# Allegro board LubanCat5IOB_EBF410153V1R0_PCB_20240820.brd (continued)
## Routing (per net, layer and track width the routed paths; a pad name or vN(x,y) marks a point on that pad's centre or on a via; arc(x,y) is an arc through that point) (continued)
MIPI_DPHY0_RX_CLKP: length 147.9
  TOP w0.114: J3.13 44.87,64.5 44.95,64.42 44.95,63.83 v2(44.68,63.56) ; v1(158.6,77.76) 158.79,77.57 159.36,77.57 159.74,77.19 159.74,76.18 159.87,76.05 160.06,76.05 160.2,76.18 160.2,77.19 160.47,77.47 162.17,77.47 162.42,77.22 164.93,77.22 arc(165,77.23) 165.07,77.28 165.08,77.29 arc(165.15,77.33) 165.22,77.35 J32.9
  ART03 w0.102: v2(44.68,63.56) 44.93,63.31 44.93,61.21 45.38,60.77 51.83,60.77 55.87,64.81 65.28,64.81 68.91,61.18 75,61.18 78.04,60.65 81.08,61.18 81.91,61.18 84.66,60.7 87.42,61.18 88.27,61.18 92.28,61.88 96.3,61.18 100.33,61.18 103.7,61.76 107.07,61.18 114.21,61.18 114.58,61.55 114.58,62.89 114.6,63.12 114.96,65.22 114.6,67.33 114.58,67.55 114.58,70.07 117.96,73.45 123.46,73.45 123.92,73.9 140.37,73.9 140.74,74.27 140.74,76.27 140.94,76.47 148.3,76.47 148.93,75.83 159.35,75.83 159.72,76.2 159.72,77.12 159.27,77.56 158.79,77.56 v1(158.6,77.76)
MIPI_DPHY0_RX_D0N: length 147.8
  TOP w0.114: J32.12 165.22,75.85 arc(165.15,75.86) 165.08,75.9 165.07,75.92 arc(165,75.96) 164.93,75.98 163.29,75.98 arc(163.12,75.94) 162.97,75.84 v1(162.81,75.69) ; J3.25 47.27,64.5 47.19,64.42 47.19,63.83 v2(47.46,63.56)
  ART03 w0.102: v1(162.81,75.69) 162.96,75.83 164.25,75.83 164.69,76.27 164.69,78.92 163.97,79.64 156.5,79.64 156.13,79.28 156.13,78.2 155.93,77.99 153.03,77.99 152.91,78.11 152.91,78.83 152.63,79.11 152.23,79.11 151.95,78.83 151.95,78.11 151.83,77.99 151.66,77.99 151.54,78.11 151.54,78.47 151.26,78.75 150.86,78.75 150.58,78.47 150.58,78.11 150.46,77.99 149.92,77.99 149.09,78.83 136.38,78.83 136.04,78.49 136.04,76.8 135.84,76.6 118.01,76.6 112.12,70.7 112.12,67.19 arc(112.11,67.17) 112.11,67.16 111.86,65.69 arc(111.85,65.61) 111.86,65.53 112.11,64.06 arc(112.11,64.05) 112.12,64.03 112.12,63.43 111.82,63.13 107.25,63.13 arc(107.24,63.13) 107.22,63.14 103.78,63.73 arc(103.7,63.74) 103.62,63.73 100.18,63.14 arc(100.16,63.13) 100.14,63.13 96.49,63.13 arc(96.47,63.13) 96.45,63.14 92.37,63.85 arc(92.28,63.85) 92.2,63.85 88.12,63.14 arc(88.1,63.13) 88.08,63.13 87.25,63.13 84.66,62.69 82.08,63.13 80.91,63.13 78.04,62.64 75.17,63.13 70.3,63.13 66.87,66.56 54,66.56 50.26,62.82 47.42,62.82 47.29,62.95 47.29,63.39 v2(47.46,63.56)
MIPI_DPHY0_RX_D0P: length 147.8
  TOP w0.114: J32.11 165.22,76.35 arc(165.15,76.33) 165.08,76.29 165.07,76.28 arc(165,76.23) 164.93,76.22 163.29,76.22 arc(163.12,76.25) 162.97,76.35 v1(162.81,76.51) ; v2(46.68,63.56) 46.95,63.83 46.95,64.42 46.87,64.5 J3.23
  ART03 w0.102: v2(46.68,63.56) 46.89,63.56 47.01,63.45 47.01,62.83 47.3,62.54 50.38,62.54 54.12,66.28 66.75,66.28 70.18,62.85 75.14,62.85 78.04,62.35 80.93,62.85 82.05,62.85 84.66,62.4 87.27,62.85 88.08,62.85 arc(88.13,62.86) 88.17,62.86 92.25,63.57 arc(92.28,63.57) 92.32,63.57 96.4,62.86 arc(96.44,62.86) 96.49,62.85 100.14,62.85 arc(100.18,62.86) 100.22,62.86 103.66,63.46 arc(103.7,63.46) 103.73,63.46 107.17,62.86 arc(107.21,62.86) 107.25,62.85 111.94,62.85 112.39,63.31 112.39,64.03 arc(112.39,64.07) 112.39,64.11 112.13,65.57 arc(112.13,65.61) 112.13,65.64 112.39,67.11 arc(112.39,67.15) 112.39,67.19 112.39,70.59 118.12,76.32 135.95,76.32 136.32,76.68 136.32,78.37 136.5,78.55 148.97,78.55 149.81,77.71 150.57,77.71 150.86,78 150.86,78.36 150.98,78.48 151.14,78.48 151.26,78.36 151.26,78 151.55,77.71 151.95,77.71 152.23,78 152.23,78.71 152.35,78.83 152.52,78.83 152.63,78.71 152.63,78 152.92,77.71 156.05,77.71 156.41,78.08 156.41,79.16 156.62,79.36 163.86,79.36 164.41,78.81 164.41,76.39 164.13,76.11 162.92,76.11 162.81,76.22 v1(162.81,76.51)
MIPI_DPHY0_RX_D1N: length 147.7
  TOP w0.114: J32.8 165.22,77.85 arc(165.15,77.86) 165.08,77.9 165.07,77.92 arc(165,77.96) 164.93,77.98 164.55,77.98 arc(164.47,77.94) 164.43,77.86 arc(164.4,77.77) 164.32,77.74 164.1,77.74 arc(164.01,77.77) 163.98,77.86 arc(163.94,77.94) 163.86,77.98 163.29,77.98 arc(163.12,77.94) 162.97,77.84 v1(162.81,77.69) ; v2(46.57,62.54) 46.28,62.84 46.28,63.97 46.39,64.09 46.39,64.42 46.47,64.5 J3.21
  ART03 w0.102: v2(46.57,62.54) 46.32,62.29 46.32,62.01 46.53,61.8 46.81,61.8 arc(46.89,61.84) 46.93,61.92 arc(46.96,62.01) 47.05,62.04 47.22,62.04 arc(47.3,62.01) 47.33,61.92 arc(47.37,61.84) 47.45,61.8 47.62,61.8 arc(47.71,61.84) 47.74,61.92 arc(47.78,62.01) 47.86,62.04 48.03,62.04 arc(48.11,62.01) 48.15,61.92 arc(48.18,61.84) 48.27,61.8 48.44,61.8 arc(48.52,61.84) 48.55,61.92 arc(48.59,62.01) 48.67,62.04 48.84,62.04 arc(48.93,62.01) 48.96,61.92 arc(49,61.84) 49.08,61.8 49.25,61.8 arc(49.33,61.84) 49.37,61.92 arc(49.4,62.01) 49.49,62.04 49.65,62.04 arc(49.74,62.01) 49.77,61.92 arc(49.81,61.84) 49.89,61.8 51.23,61.8 55.26,65.83 65.88,65.83 69.41,62.3 75.09,62.3 78.04,61.78 80.98,62.3 82,62.3 84.66,61.83 87.32,62.3 88.17,62.3 92.28,63.01 96.4,62.3 100.23,62.3 103.7,62.9 107.17,62.3 113.08,62.3 113.28,62.5 113.28,64.24 arc(113.28,64.26) 113.28,64.27 113.04,65.64 arc(113.04,65.73) 113.04,65.81 113.28,67.18 arc(113.28,67.2) 113.28,67.22 113.28,70.53 117.83,75.07 123.18,75.07 123.73,75.63 136.74,75.63 137.01,75.9 137.01,77.38 137.31,77.69 137.9,77.69 138.18,77.41 138.18,76.05 138.3,75.94 138.76,75.94 138.96,76.14 138.96,77.16 139.33,77.53 148.98,77.53 149.38,77.13 156.95,77.13 157.15,77.33 157.15,78.3 157.58,78.73 161.7,78.73 162.1,78.32 162.1,77.48 162.36,77.23 163.47,77.23 163.68,77.43 163.68,77.76 163.47,77.96 163.08,77.96 v1(162.81,77.69)
MIPI_DPHY0_RX_D1P: length 147.7
  TOP w0.114: v2(45.79,62.54) 46.04,62.79 46.04,64.07 46.15,64.19 46.15,64.42 46.07,64.5 J3.19 ; J32.7 165.22,78.35 arc(165.15,78.33) 165.08,78.29 165.07,78.28 arc(165,78.23) 164.93,78.22 163.29,78.22 arc(163.12,78.25) 162.97,78.35 v1(162.81,78.51)
  ART03 w0.102: v1(162.81,78.51) 163.08,78.24 163.59,78.24 163.96,77.87 163.96,77.32 163.59,76.95 162.24,76.95 161.82,77.37 161.82,78.21 161.58,78.45 157.7,78.45 157.43,78.18 157.43,77.22 157.06,76.85 149.26,76.85 148.87,77.25 139.45,77.25 139.24,77.04 139.24,76.02 138.88,75.66 138.19,75.66 137.9,75.94 137.9,77.29 137.79,77.41 137.43,77.41 137.29,77.27 137.29,75.78 136.86,75.35 123.85,75.35 123.29,74.79 117.95,74.79 113.56,70.41 113.56,67.22 arc(113.56,67.17) 113.56,67.13 113.32,65.76 arc(113.32,65.73) 113.32,65.69 113.56,64.32 arc(113.56,64.28) 113.56,64.24 113.56,62.38 113.2,62.02 107.14,62.02 103.7,62.61 100.25,62.02 96.37,62.02 92.28,62.73 88.2,62.02 87.34,62.02 84.66,61.55 81.98,62.02 81,62.02 78.04,61.5 75.07,62.02 69.29,62.02 65.76,65.55 55.37,65.55 51.35,61.52 46.41,61.52 46.04,61.89 46.04,62.29 v2(45.79,62.54)
MIPI_DPHY0_RX_D2N: length 147.9
  TOP w0.114: v2(44.26,62.55) 43.99,62.82 43.99,64.42 44.07,64.5 J3.9 ; J32.17 165.22,73.35 arc(165.15,73.36) 165.08,73.4 165.07,73.42 arc(165,73.46) 164.93,73.48 163.29,73.48 arc(163.12,73.44) 162.97,73.34 v1(162.81,73.19)
  ART03 w0.102: v2(44.26,62.55) 44.14,62.67 44.14,63.25 43.75,63.64 43.06,63.64 42.7,63.28 42.7,60.33 43.17,59.86 52.37,59.86 56.24,63.72 65.14,63.72 68.54,60.31 74.92,60.31 78.04,59.77 81.15,60.31 81.83,60.31 84.66,59.82 87.49,60.31 88.34,60.31 92.28,61 96.22,60.31 100.4,60.31 103.7,60.89 106.99,60.31 114.42,60.31 115.32,61.21 115.32,62.86 115.33,63.02 115.71,65.22 115.33,67.42 115.32,67.59 115.32,69.19 118.61,72.48 141.34,72.48 141.71,72.85 141.71,73.98 141.91,74.18 143.15,74.18 143.93,74.95 159.77,74.95 160.07,74.65 160.07,73.67 160.44,73.31 162.7,73.31 v1(162.81,73.19)
MIPI_DPHY0_RX_D2P: length 147.8
  TOP w0.114: J3.7 43.67,64.5 43.75,64.42 43.75,62.82 v2(43.48,62.55) ; J32.16 165.22,73.85 arc(165.15,73.83) 165.08,73.79 165.07,73.78 arc(165,73.73) 164.93,73.72 163.29,73.72 arc(163.12,73.75) 162.97,73.85 v1(162.81,74.01)
  ART03 w0.102: v1(162.81,74.01) 162.81,73.69 162.71,73.59 162.22,73.59 arc(162.15,73.61) 162.12,73.68 arc(162.09,73.75) 162.03,73.78 161.81,73.78 arc(161.74,73.75) 161.71,73.68 arc(161.69,73.61) 161.62,73.59 160.55,73.59 160.35,73.79 160.35,74.77 159.88,75.23 143.81,75.23 143.04,74.46 141.79,74.46 141.43,74.1 141.43,72.96 141.22,72.76 118.49,72.76 115.04,69.31 115.04,67.57 115.05,67.39 115.43,65.22 115.05,63.06 115.04,62.87 115.04,61.33 114.3,60.59 107.02,60.59 103.7,61.17 100.38,60.59 96.25,60.59 92.28,61.28 88.32,60.59 87.47,60.59 84.66,60.11 81.86,60.59 81.13,60.59 78.04,60.06 74.95,60.59 68.66,60.59 65.25,64 56.12,64 52.26,60.14 43.28,60.14 42.98,60.44 42.98,60.67 arc(43.01,60.75) 43.09,60.78 arc(43.17,60.82) 43.21,60.9 43.21,61.08 arc(43.17,61.16) 43.09,61.19 arc(43.01,61.22) 42.98,61.31 42.98,61.48 arc(43.01,61.56) 43.09,61.6 arc(43.17,61.63) 43.21,61.71 43.21,61.89 arc(43.17,61.97) 43.09,62 arc(43.01,62.04) 42.98,62.12 42.98,63.16 43.18,63.36 43.63,63.36 43.86,63.13 43.86,62.65 43.76,62.55 v2(43.48,62.55)
MIPI_DPHY0_RX_D3N: length 147.8
  TOP w0.114: J32.20 165.22,71.85 arc(165.15,71.86) 165.08,71.9 165.07,71.92 arc(165,71.96) 164.93,71.98 162.02,71.98 arc(161.85,71.94) 161.7,71.84 v1(161.54,71.69) ; J3.5 43.27,64.5 43.19,64.42 43.19,64 42.82,63.63 41.49,63.63 v2(41.22,63.36)
  ART03 w0.102: v2(41.22,63.36) 41.47,63.61 41.76,63.61 42.04,63.33 42.04,59.84 42.86,59.02 52.98,59.02 56.95,62.98 64.47,62.98 67.94,59.5 74.84,59.5 arc(74.85,59.5) 74.87,59.5 77.96,58.96 arc(78.04,58.96) 78.12,58.96 81.2,59.5 arc(81.22,59.5) 81.24,59.5 81.75,59.5 arc(81.76,59.5) 81.78,59.5 84.58,59.01 arc(84.66,59.01) 84.74,59.01 87.54,59.5 arc(87.56,59.5) 87.58,59.5 88.41,59.5 92.28,60.17 96.15,59.5 100.47,59.5 103.7,60.06 106.92,59.5 114.78,59.5 116.05,60.77 116.05,62.86 arc(116.05,62.88) 116.06,62.9 116.45,65.14 arc(116.45,65.22) 116.45,65.31 116.06,67.55 arc(116.05,67.57) 116.05,67.59 116.05,68.38 119.42,71.74 142.95,71.74 143.89,72.68 143.89,73.64 144.24,73.99 157.93,73.99 159.97,71.96 161.28,71.96 v1(161.54,71.69)
MIPI_DPHY0_RX_D3P: length 147.8
  TOP w0.114: v2(41.22,64.14) 41.49,63.87 42.72,63.87 42.95,64.1 42.95,64.42 42.87,64.5 J3.3 ; J32.19 165.22,72.35 arc(165.15,72.33) 165.08,72.29 165.07,72.28 arc(165,72.23) 164.93,72.22 162.02,72.22 arc(161.85,72.25) 161.7,72.35 v1(161.54,72.51)
  ART03 w0.102: v2(41.22,64.14) 41.47,63.89 41.87,63.89 42.32,63.45 42.32,59.96 42.98,59.3 43.33,59.3 arc(43.39,59.32) 43.42,59.39 arc(43.44,59.45) 43.5,59.48 43.73,59.48 arc(43.8,59.45) 43.82,59.39 arc(43.85,59.32) 43.91,59.3 44.14,59.3 arc(44.2,59.32) 44.23,59.39 arc(44.25,59.45) 44.32,59.48 44.55,59.48 arc(44.61,59.45) 44.63,59.39 arc(44.66,59.32) 44.72,59.3 52.87,59.3 56.83,63.26 64.58,63.26 68.06,59.78 74.84,59.78 arc(74.88,59.78) 74.92,59.77 78,59.24 arc(78.04,59.24) 78.07,59.24 81.16,59.77 arc(81.2,59.78) 81.24,59.78 81.75,59.78 arc(81.79,59.78) 81.83,59.77 84.63,59.29 arc(84.66,59.29) 84.7,59.29 87.5,59.77 arc(87.54,59.78) 87.58,59.78 88.39,59.78 92.28,60.46 96.18,59.78 100.45,59.78 103.7,60.35 106.95,59.78 114.67,59.78 115.77,60.89 115.77,62.86 arc(115.77,62.9) 115.78,62.95 116.17,65.19 arc(116.17,65.22) 116.17,65.26 115.78,67.5 arc(115.77,67.54) 115.77,67.59 115.77,68.49 119.3,72.02 142.84,72.02 143.61,72.8 143.61,73.75 144.13,74.27 158.05,74.27 160.08,72.24 161.28,72.24 v1(161.54,72.51)
MIPI_DPHY0_TX_CLKN: length 66.4
  TOP w0.114: v1(8.99,71.42) 8.7,71.7 7.94,71.7 7.81,71.57 J14.24 ; J3.41 50.47,64.5 50.39,64.42 50.39,60.53 49.2,59.34 37.14,59.34 36.86,59.61 36.86,60.14 36.73,60.28 36.54,60.28 36.41,60.14 36.41,59.61 36.13,59.34 35.7,59.34 v1(35.43,59.07)
  ART03 w0.102: v1(35.43,59.07) 35.16,59.34 33.7,59.34 33.44,59.6 21.89,59.6 21.56,59.93 21.56,62.38 21.37,62.58 15.54,62.58 15.14,62.98 15.14,67.48 14.94,67.68 11.72,67.68 11.35,68.05 11.35,68.55 11.64,68.83 12.68,68.83 12.8,68.95 12.8,69.12 12.68,69.24 11.64,69.24 11.35,69.52 11.35,69.92 11.64,70.2 12.68,70.2 12.8,70.32 12.8,70.49 12.68,70.61 11.64,70.61 11.35,70.89 11.35,71.47 11.15,71.67 9.24,71.67 v1(8.99,71.42)
MIPI_DPHY0_TX_CLKP: length 66.4
  TOP w0.114: v1(35.43,59.89) 35.75,59.58 36.03,59.58 36.17,59.71 36.17,60.24 36.44,60.52 36.83,60.52 37.11,60.24 37.11,59.71 37.24,59.58 49.1,59.58 50.15,60.63 50.15,63.32 arc(50.11,63.43) 49.99,63.48 arc(49.88,63.52) 49.83,63.63 49.83,63.77 arc(49.88,63.89) 49.99,63.93 arc(50.11,63.98) 50.15,64.09 50.15,64.42 50.07,64.5 J3.39 ; v1(8.99,72.23) 8.7,71.94 7.94,71.94 7.81,72.07 J14.23
  ART03 w0.102: v1(8.99,72.23) 9.27,71.95 11.27,71.95 11.63,71.58 11.63,71.01 11.75,70.89 12.8,70.89 13.08,70.61 13.08,70.21 12.8,69.93 11.75,69.93 11.63,69.81 11.63,69.64 11.75,69.52 12.8,69.52 13.08,69.24 13.08,68.84 12.8,68.55 11.75,68.55 11.63,68.43 11.63,68.16 11.84,67.96 15.05,67.96 15.42,67.59 15.42,63.1 15.66,62.85 21.49,62.85 21.84,62.5 21.84,60.05 22.01,59.88 33.55,59.88 33.81,59.62 35.16,59.62 v1(35.43,59.89)
MIPI_DPHY0_TX_D0N: length 66.4
  TOP w0.114: J14.27 7.81,70.07 7.94,70.2 9.26,70.2 v1(9.58,69.89) ; J3.51 52.47,64.5 52.39,64.42 52.39,59.7 49.75,57.05 44,57.05 43.87,56.92 43.87,56.58 43.59,56.3 43.2,56.3 42.93,56.58 42.93,56.92 42.79,57.05 42.55,57.05 42.42,56.92 42.42,56.45 42.14,56.17 41.75,56.17 41.48,56.45 41.48,56.92 41.34,57.05 39.91,57.05 v1(39.62,56.76)
  ART03 w0.102: v1(39.62,56.76) 39.27,57.11 33.97,57.11 33.63,57.46 33.63,58.32 33.44,58.51 20.89,58.51 20.56,58.85 20.56,61.39 20.23,61.71 14.78,61.71 14.4,62.09 14.4,66.55 14.11,66.84 10.73,66.84 10.36,67.21 10.36,69.98 10.16,70.18 9.87,70.18 v1(9.58,69.89)
MIPI_DPHY0_TX_D0P: length 66.5
  TOP w0.114: J3.49 52.07,64.5 52.15,64.42 52.15,59.8 49.65,57.29 43.9,57.29 43.63,57.02 43.63,56.68 43.49,56.54 43.3,56.54 43.17,56.68 43.17,57.02 42.89,57.29 42.45,57.29 42.18,57.02 42.18,56.55 42.04,56.42 41.85,56.42 41.72,56.55 41.72,57.02 41.44,57.29 39.91,57.29 v1(39.62,57.58) ; J14.26 7.81,70.57 7.94,70.44 9.31,70.44 v1(9.58,70.71)
  ART03 w0.102: v1(9.58,70.71) 9.82,70.46 10.28,70.46 10.64,70.1 10.64,67.32 10.85,67.12 14.22,67.12 14.68,66.66 14.68,62.21 14.9,61.99 20.35,61.99 20.83,61.5 20.83,58.96 21.01,58.79 33.55,58.79 33.91,58.43 33.91,57.57 34.09,57.39 34.4,57.39 arc(34.49,57.43) 34.53,57.52 arc(34.56,57.61) 34.65,57.65 34.81,57.65 arc(34.9,57.61) 34.93,57.52 arc(34.97,57.43) 35.06,57.39 35.21,57.39 arc(35.3,57.43) 35.34,57.52 arc(35.38,57.61) 35.47,57.65 35.62,57.65 arc(35.71,57.61) 35.75,57.52 arc(35.78,57.43) 35.87,57.39 39.44,57.39 v1(39.62,57.58)
MIPI_DPHY0_TX_D1N: length 66.4
  TOP w0.114: v1(37.72,57.91) 38.01,58.19 49.47,58.19 51.59,60.32 51.59,64.42 51.67,64.5 J3.47 ; v1(9.75,72.92) 9.46,73.2 7.94,73.2 7.81,73.07 J14.21
  ART03 w0.102: v1(37.72,57.91) 37.45,58.17 36.31,58.17 35.94,58.54 35.94,60.43 35.5,60.87 22.85,60.87 22.53,61.19 22.53,63.63 22.34,63.82 16.54,63.82 16.17,64.19 16.17,68.11 15.79,68.49 13.91,68.49 13.54,68.86 13.54,71.54 13.42,71.66 12.53,71.66 12.24,71.94 12.24,72.34 12.53,72.63 13.42,72.63 13.54,72.75 13.54,72.98 13.33,73.18 10.02,73.18 v1(9.75,72.92)
MIPI_DPHY0_TX_D1P: length 66.4
  TOP w0.114: J3.45 51.27,64.5 51.35,64.42 51.35,60.42 49.37,58.43 38.01,58.43 v1(37.72,58.72) ; v1(9.75,73.73) 9.46,73.44 7.94,73.44 7.81,73.57 J14.20
  ART03 w0.102: v1(9.75,73.73) 10.02,73.46 11.66,73.46 arc(11.73,73.49) 11.75,73.56 arc(11.78,73.62) 11.85,73.65 12.07,73.65 arc(12.13,73.62) 12.16,73.56 arc(12.19,73.49) 12.25,73.46 12.47,73.46 arc(12.54,73.49) 12.57,73.56 arc(12.59,73.62) 12.66,73.65 12.88,73.65 arc(12.95,73.62) 12.97,73.56 arc(13,73.49) 13.07,73.46 13.45,73.46 13.82,73.09 13.82,72.63 13.53,72.35 12.64,72.35 12.52,72.23 12.52,72.06 12.64,71.94 13.53,71.94 13.82,71.66 13.82,68.98 14.02,68.77 15.9,68.77 16.45,68.23 16.45,64.3 16.65,64.1 22.46,64.1 22.81,63.74 22.81,61.31 22.96,61.15 35.61,61.15 36.22,60.54 36.22,58.66 36.42,58.45 37.45,58.45 v1(37.72,58.72)
MIPI_DPHY0_TX_D2N: length 66.4
  TOP w0.114: v1(8.9,74.42) 8.61,74.7 7.94,74.7 7.81,74.57 J14.18 ; v1(37.72,60.18) 38.02,60.48 47.82,60.48 49.19,61.86 49.19,64.42 49.27,64.5 J3.35
  ART03 w0.102: v1(8.9,74.42) 9.17,74.68 9.84,74.68 10.29,74.23 14.12,74.23 14.33,74.03 14.33,69.65 14.69,69.28 16.8,69.28 17.17,68.91 17.17,65.19 17.55,64.81 23.1,64.81 23.39,64.52 23.39,62.12 23.8,61.71 24.52,61.71 24.8,61.99 24.8,62.61 24.92,62.73 25.09,62.73 25.21,62.61 25.21,61.98 25.48,61.71 25.96,61.71 26.25,61.99 26.25,62.61 26.37,62.73 26.54,62.73 26.65,62.61 26.65,61.99 26.94,61.71 27.34,61.71 27.62,61.99 27.62,62.63 27.72,62.73 27.92,62.73 28.03,62.63 28.03,61.99 28.31,61.71 30.05,61.71 30.33,61.99 30.33,62.58 30.45,62.7 30.62,62.7 30.74,62.58 30.74,61.99 31.02,61.71 31.53,61.71 31.81,61.99 31.81,62.61 31.93,62.73 32.1,62.73 32.22,62.61 32.22,61.99 32.5,61.71 35.7,61.71 36.96,60.45 37.45,60.45 v1(37.72,60.18)
MIPI_DPHY0_TX_D2P: length 66.4
  TOP w0.114: v1(37.72,61) 37.99,60.72 47.72,60.72 48.95,61.96 48.95,64.42 48.87,64.5 J3.33 ; v1(8.9,75.23) 8.61,74.94 7.94,74.94 7.81,75.07 J14.17
  ART03 w0.102: v1(8.9,75.23) 9.17,74.96 9.95,74.96 10.4,74.51 10.63,74.51 arc(10.7,74.54) 10.73,74.62 arc(10.76,74.69) 10.83,74.72 11.04,74.72 arc(11.11,74.69) 11.14,74.62 arc(11.17,74.54) 11.24,74.51 11.44,74.51 arc(11.51,74.54) 11.54,74.62 arc(11.57,74.69) 11.65,74.72 11.85,74.72 arc(11.92,74.69) 11.95,74.62 arc(11.98,74.54) 12.05,74.51 14.24,74.51 14.61,74.15 14.61,69.76 14.81,69.56 16.92,69.56 17.45,69.03 17.45,65.31 17.67,65.09 23.22,65.09 23.67,64.63 23.67,62.23 23.92,61.99 24.4,61.99 24.52,62.11 24.52,62.72 24.8,63.01 25.2,63.01 25.49,62.72 25.49,62.1 25.59,61.99 25.85,61.99 25.97,62.11 25.97,62.72 26.25,63.01 26.65,63.01 26.93,62.72 26.93,62.11 27.05,61.99 27.22,61.99 27.34,62.11 27.34,62.74 27.61,63.01 28.04,63.01 28.31,62.74 28.31,62.11 28.42,61.99 29.93,61.99 30.05,62.11 30.05,62.7 30.33,62.98 30.73,62.98 31.02,62.7 31.02,62.11 31.13,61.99 31.42,61.99 31.54,62.11 31.54,62.72 31.82,63.01 32.22,63.01 32.5,62.72 32.5,62.11 32.62,61.99 35.81,61.99 37.08,60.73 37.45,60.73 v1(37.72,61)
MIPI_DPHY0_TX_D3N: length 66.4
  TOP w0.114: v1(8.58,68.36) 8.29,68.65 7.89,68.65 7.81,68.57 J14.30 ; J3.31 48.47,64.5 48.39,64.42 48.39,62.66 47.36,61.62 39.96,61.62 v1(39.67,61.33)
  ART03 w0.102: v1(8.58,68.36) 8.31,68.63 7.85,68.63 7.62,68.4 7.62,68.18 arc(7.65,68.1) 7.73,68.06 arc(7.82,68.03) 7.85,67.95 7.85,67.77 arc(7.82,67.69) 7.73,67.66 arc(7.65,67.62) 7.62,67.54 7.62,67.36 arc(7.65,67.28) 7.73,67.25 arc(7.82,67.22) 7.85,67.13 7.85,66.96 arc(7.82,66.88) 7.73,66.84 arc(7.65,66.81) 7.62,66.73 7.62,66.44 7.85,66.21 13.16,66.21 13.84,65.52 13.84,61.46 14.05,61.25 19.38,61.25 19.84,60.79 19.84,58.04 20.13,57.75 32.46,57.75 33.58,56.63 38.89,56.63 39.5,56.02 40.65,56.02 41.05,56.42 41.05,58.6 arc(41.01,58.7) 40.91,58.74 arc(40.81,58.78) 40.77,58.88 40.77,59.01 arc(40.81,59.11) 40.91,59.15 arc(41.01,59.19) 41.05,59.29 41.05,59.42 arc(41.01,59.51) 40.91,59.56 arc(40.81,59.6) 40.77,59.7 40.77,59.82 arc(40.81,59.92) 40.91,59.96 arc(41.01,60) 41.05,60.1 41.05,60.23 arc(41.01,60.33) 40.91,60.37 arc(40.81,60.41) 40.77,60.51 40.77,60.63 arc(40.81,60.73) 40.91,60.77 arc(41.01,60.82) 41.05,60.91 41.05,61.27 40.71,61.6 39.94,61.6 v1(39.67,61.33)
MIPI_DPHY0_TX_D3P: length 66.5
  TOP w0.114: v1(39.67,62.15) 39.96,61.86 47.26,61.86 48.15,62.76 48.15,64.42 48.07,64.5 J3.29 ; J14.29 7.81,69.07 7.99,68.89 8.29,68.89 v1(8.58,69.18)
  ART03 w0.102: v1(8.58,69.18) 8.31,68.91 7.73,68.91 7.34,68.52 7.34,66.32 7.73,65.93 13.04,65.93 13.56,65.4 13.56,61.34 13.93,60.97 19.26,60.97 19.56,60.67 19.56,57.92 20.02,57.47 32.35,57.47 33.46,56.35 38.77,56.35 39.38,55.74 40.77,55.74 41.33,56.3 41.33,61.38 40.82,61.88 39.94,61.88 v1(39.67,62.15)
MIPI_DPHY1_RX_CLKN: length 141.2
  TOP w0.114: v1(61.12,58.69) 60.83,58.98 60.83,62.17 59.59,63.41 59.59,64.42 59.67,64.5 J3.87
  ART03 w0.102: v1(61.12,58.69) 60.96,58.69 60.85,58.58 60.85,57.75 61.06,57.55 61.61,57.55 arc(61.72,57.59) 61.76,57.7 arc(61.81,57.81) 61.92,57.85 62.02,57.85 arc(62.13,57.81) 62.17,57.7 arc(62.21,57.59) 62.32,57.55 62.96,57.55 64.76,55.74 68.12,55.74 70.23,56.11 72.35,55.74 79.06,55.74 81.36,56.14 83.65,55.74 85.21,55.74 87.75,56.18 90.28,55.74 91.28,55.74 93.8,56.18 96.33,55.74 97.33,55.74 99.85,56.18 102.38,55.74 103.37,55.74 105.9,56.18 108.42,55.74 109.37,55.74 111.92,56.19 114.47,55.74 119.26,55.74 119.66,56.14 119.66,63.63 120.56,64.53 146.46,64.53 146.66,64.73 146.66,69.37 147.28,69.99 156.51,69.99 158.65,67.86 165.87,67.86 166.14,68.13 166.14,73.12 167.26,74.24 168.9,74.24 v1(169.16,74.51)
  BOTTOM w0.114: J33.10 166.74,74.35 166.87,74.22 168.88,74.22 v1(169.16,74.51)
MIPI_DPHY1_RX_CLKP: length 141.2
  TOP w0.114: J3.85 59.27,64.5 59.35,64.42 59.35,63.31 60.59,62.07 60.59,58.98 v1(60.3,58.69)
  ART03 w0.102: v1(169.16,73.69) 168.9,73.96 167.38,73.96 166.42,73 166.42,68.01 165.99,67.58 158.53,67.58 156.4,69.71 147.4,69.71 146.94,69.26 146.94,64.62 146.57,64.25 120.68,64.25 119.94,63.51 119.94,56.02 119.38,55.46 114.44,55.46 111.92,55.9 109.39,55.46 108.39,55.46 105.9,55.9 103.4,55.46 102.35,55.46 99.85,55.9 97.35,55.46 96.3,55.46 93.8,55.9 91.31,55.46 90.26,55.46 87.75,55.9 85.23,55.46 83.62,55.46 81.36,55.86 79.09,55.46 72.32,55.46 70.23,55.83 68.14,55.46 64.64,55.46 62.84,57.27 60.94,57.27 60.57,57.63 60.57,58.42 v1(60.3,58.69)
  BOTTOM w0.114: J33.9 166.74,73.85 166.87,73.98 168.88,73.98 v1(169.16,73.69)
MIPI_DPHY1_RX_D0N: length 141.2
  TOP w0.114: J3.95 61.27,64.5 61.19,64.42 61.19,64 63.23,61.96 63.23,60.07 v1(63.52,59.78)
  ART03 w0.102: v1(63.52,59.78) 63.25,59.51 63.25,58.73 63.45,58.54 arc(63.52,58.51) 63.59,58.54 arc(63.66,58.57) 63.72,58.54 63.87,58.39 arc(63.9,58.32) 63.87,58.25 arc(63.84,58.18) 63.87,58.11 64.02,57.97 arc(64.09,57.94) 64.16,57.97 arc(64.23,57.99) 64.3,57.97 64.45,57.82 arc(64.48,57.75) 64.45,57.68 arc(64.42,57.61) 64.45,57.54 65.38,56.61 68.05,56.61 70.23,56.99 72.42,56.61 78.99,56.61 81.36,57.02 83.72,56.61 85.14,56.61 87.75,57.06 90.36,56.61 91.21,56.61 93.8,57.06 96.4,56.61 97.25,56.61 99.85,57.06 102.45,56.61 103.3,56.61 105.9,57.06 108.49,56.61 109.29,56.61 111.92,57.06 114.54,56.61 117.28,56.61 117.78,57.1 117.78,57.99 118.72,58.93 118.72,66.11 119.18,66.56 120.51,66.56 121.88,67.93 124.4,67.93 124.76,67.57 124.76,65.8 124.97,65.6 136.82,65.6 136.94,65.72 136.94,66.61 137.22,66.89 137.62,66.89 137.9,66.61 137.9,65.72 138.02,65.6 138.19,65.6 138.31,65.72 138.31,66.61 138.59,66.89 138.99,66.89 139.28,66.61 139.28,65.72 139.4,65.6 139.73,65.6 139.83,65.7 139.83,67.62 140.19,67.99 142.99,67.99 145.99,70.99 156.89,70.99 158.89,68.99 164.69,68.99 165.35,69.65 165.35,73.44 167.14,75.22 167.81,75.22 v1(168.09,75.51)
  BOTTOM w0.114: J33.12 166.74,75.35 166.87,75.22 167.8,75.22 v1(168.09,75.51)
MIPI_DPHY1_RX_D0P: length 141.2
  TOP w0.114: J3.93 60.87,64.5 60.95,64.42 60.95,63.9 62.99,61.86 62.99,60.07 v1(62.7,59.78)
  ART03 w0.102: v1(62.7,59.78) 62.97,59.51 62.97,58.62 65.26,56.33 68.07,56.33 70.23,56.7 72.4,56.33 79.01,56.33 81.36,56.73 83.7,56.33 85.16,56.33 87.75,56.78 90.33,56.33 91.23,56.33 93.8,56.77 96.38,56.33 97.28,56.33 99.85,56.77 102.43,56.33 103.32,56.33 105.9,56.77 108.47,56.33 109.32,56.33 111.92,56.78 114.52,56.33 117.4,56.33 118.06,56.99 118.06,57.88 119,58.82 119,65.99 119.29,66.28 120.62,66.28 122,67.66 124.28,67.66 124.49,67.45 124.49,65.69 124.85,65.32 136.94,65.32 137.22,65.6 137.22,66.49 137.34,66.61 137.51,66.61 137.63,66.49 137.63,65.6 137.91,65.32 138.31,65.32 138.59,65.6 138.59,66.49 138.71,66.61 138.88,66.61 139,66.49 139,65.6 139.28,65.32 139.84,65.32 140.11,65.58 140.11,67.5 140.31,67.71 143.1,67.71 146.11,70.71 156.77,70.71 158.78,68.71 164.8,68.71 165.63,69.53 165.63,73.32 167.26,74.94 167.83,74.94 v1(168.09,74.69)
  BOTTOM w0.114: v1(168.09,74.69) 167.8,74.98 166.87,74.98 166.74,74.85 J33.11
MIPI_DPHY1_RX_D1N: length 141.3
  TOP w0.114: J3.91 60.47,64.5 60.39,64.42 60.39,63.73 61.98,62.14 61.98,57.07 v1(62.26,56.78)
  ART03 w0.102: v1(168.09,73.51) 167.82,73.24 167.29,73.24 166.98,72.93 166.98,72.15 167.74,71.39 167.74,67.22 167.37,66.85 158.34,66.85 157.94,67.25 151.71,67.25 151.59,67.38 151.59,68.09 151.32,68.35 148.08,68.35 147.73,68 147.73,63.99 147.48,63.74 121.62,63.74 120.83,62.96 120.83,55.07 120.59,54.83 114.39,54.83 111.92,55.26 109.44,54.83 108.34,54.83 105.9,55.25 103.45,54.83 102.3,54.83 99.85,55.25 97.41,54.83 96.25,54.83 93.8,55.25 91.36,54.83 90.2,54.83 87.75,55.25 85.29,54.83 83.57,54.83 81.36,55.21 79.14,54.83 72.27,54.83 70.23,55.18 68.2,54.83 63.87,54.83 arc(63.79,54.86) 63.76,54.94 arc(63.72,55.02) 63.64,55.06 63.46,55.06 arc(63.38,55.02) 63.35,54.94 arc(63.32,54.86) 63.23,54.83 63.06,54.83 arc(62.98,54.86) 62.94,54.94 arc(62.91,55.02) 62.83,55.06 62.65,55.06 arc(62.57,55.02) 62.54,54.94 arc(62.5,54.86) 62.42,54.83 62.19,54.83 62,55.03 62,56.52 v1(62.26,56.78)
  BOTTOM w0.114: J33.8 166.74,73.35 166.87,73.22 167.8,73.22 v1(168.09,73.51)
MIPI_DPHY1_RX_D1P: length 141.2
  TOP w0.114: v1(61.45,56.78) 61.73,57.07 61.73,62.04 60.15,63.63 60.15,64.42 60.07,64.5 J3.89
  ART03 w0.102: v1(168.09,72.69) 167.82,72.96 167.41,72.96 167.26,72.81 167.26,72.27 168.02,71.5 168.02,67.11 167.48,66.57 158.22,66.57 157.82,66.97 151.6,66.97 151.31,67.26 151.31,67.97 151.21,68.07 148.19,68.07 148.01,67.88 148.01,63.87 147.6,63.46 121.73,63.46 121.11,62.84 121.11,54.96 120.7,54.55 114.36,54.55 111.92,54.97 109.47,54.55 108.31,54.55 105.9,54.97 103.48,54.55 102.27,54.55 99.85,54.97 97.43,54.55 96.23,54.55 93.8,54.97 91.38,54.55 90.18,54.55 87.75,54.97 85.31,54.55 83.54,54.55 81.36,54.93 79.17,54.55 72.24,54.55 70.23,54.9 68.22,54.55 62.08,54.55 61.72,54.91 61.72,56.52 v1(61.45,56.78)
  BOTTOM w0.114: v1(168.09,72.69) 167.8,72.98 166.87,72.98 166.74,72.85 J33.7
MIPI_DPHY1_RX_D2N: length 141.1
  TOP w0.114: v1(59.85,60.37) 59.59,60.63 59.59,62.24 58.79,63.04 58.79,64.42 58.87,64.5 J3.83
  ART03 w0.102: v1(59.85,60.37) 59.58,60.1 59.58,59.58 59.79,59.37 60.76,59.37 60.97,59.58 60.97,60.38 61.38,60.8 63.6,60.8 66.9,57.5 67.97,57.5 70.23,57.89 72.5,57.5 78.91,57.5 81.36,57.92 83.8,57.5 85.06,57.5 87.75,57.96 90.43,57.5 91.13,57.5 93.8,57.96 96.48,57.5 97.18,57.5 99.85,57.96 102.53,57.5 103.22,57.5 105.9,57.96 108.57,57.5 109.22,57.5 111.92,57.96 114.62,57.5 115.71,57.5 117.83,59.62 117.83,67.52 119.52,69.2 124.97,69.2 125.43,68.75 142.49,68.75 145.74,71.99 157.05,71.99 159.2,69.85 164.21,69.85 164.57,70.21 164.57,73.9 166.32,75.66 166.32,77.42 166.66,77.76 167.24,77.76 arc(167.32,77.8) 167.35,77.88 arc(167.39,77.96) 167.47,77.99 167.64,77.99 arc(167.73,77.96) 167.76,77.88 arc(167.79,77.8) 167.87,77.76 168.05,77.76 arc(168.13,77.8) 168.17,77.88 arc(168.2,77.96) 168.28,77.99 168.46,77.99 arc(168.54,77.96) 168.57,77.88 arc(168.61,77.8) 168.69,77.76 168.92,77.76 v1(169.16,78.01)
  BOTTOM w0.114: J33.17 166.74,77.85 166.87,77.72 168.88,77.72 v1(169.16,78.01)
MIPI_DPHY1_RX_D2P: length 141.1
  TOP w0.114: v1(59.03,60.37) 59.35,60.68 59.35,62.15 58.55,62.94 58.55,64.42 58.47,64.5 J3.81
  ART03 w0.102: v1(59.03,60.37) 59.3,60.1 59.3,59.46 59.67,59.1 60.88,59.1 61.24,59.46 61.24,60.27 61.49,60.52 63.49,60.52 66.79,57.22 67.99,57.22 70.23,57.6 72.47,57.22 78.94,57.22 81.36,57.64 83.77,57.22 85.08,57.22 87.75,57.68 90.41,57.22 91.15,57.22 93.8,57.68 96.46,57.22 97.2,57.22 99.85,57.68 102.5,57.22 103.25,57.22 105.9,57.68 108.54,57.22 109.24,57.22 111.92,57.68 114.59,57.22 115.82,57.22 118.11,59.5 118.11,67.4 119.63,68.93 124.85,68.93 125.31,68.47 142.61,68.47 145.85,71.71 156.94,71.71 159.08,69.57 164.32,69.57 164.85,70.09 164.85,73.79 166.6,75.54 166.6,77.31 166.77,77.48 168.87,77.48 v1(169.16,77.19)
  BOTTOM w0.114: v1(169.16,77.19) 168.88,77.48 166.87,77.48 166.74,77.35 J33.16
MIPI_DPHY1_RX_D3N: length 141.2
  TOP w0.114: J3.79 58.07,64.5 57.99,64.42 57.99,62.05 v1(58.26,61.78)
  ART03 w0.102: v1(168.09,79.51) 167.82,79.24 166.06,79.24 165.56,78.73 165.56,76.05 163.75,74.25 163.75,71.2 163.49,70.93 159.81,70.93 157.75,72.99 145.32,72.99 143.21,70.88 132.64,70.88 132.36,70.6 132.36,69.86 132.24,69.74 132.07,69.74 131.96,69.86 131.96,70.6 131.67,70.88 131.27,70.88 130.99,70.6 130.99,69.86 130.87,69.74 130.7,69.74 130.58,69.86 130.58,70.6 130.3,70.88 120.05,70.88 117.04,67.87 117.04,60.07 115.29,58.32 114.7,58.32 arc(114.69,58.32) 114.67,58.32 112,58.79 arc(111.92,58.79) 111.83,58.79 109.16,58.32 arc(109.14,58.32) 109.13,58.32 108.66,58.32 arc(108.64,58.32) 108.62,58.32 105.98,58.78 arc(105.9,58.79) 105.81,58.78 103.17,58.32 arc(103.15,58.32) 103.13,58.32 102.61,58.32 arc(102.6,58.32) 102.58,58.32 99.93,58.78 arc(99.85,58.79) 99.77,58.78 97.12,58.32 arc(97.1,58.32) 97.09,58.32 96.57,58.32 arc(96.55,58.32) 96.53,58.32 93.89,58.78 arc(93.8,58.79) 93.72,58.78 91.08,58.32 arc(91.06,58.32) 91.04,58.32 90.52,58.32 arc(90.51,58.32) 90.49,58.32 87.83,58.79 arc(87.75,58.79) 87.66,58.79 85.01,58.32 arc(84.99,58.32) 84.97,58.32 83.89,58.32 arc(83.87,58.32) 83.85,58.32 81.44,58.74 arc(81.36,58.75) 81.27,58.74 78.86,58.32 arc(78.84,58.32) 78.82,58.32 72.59,58.32 arc(72.57,58.32) 72.55,58.32 70.32,58.71 arc(70.23,58.72) 70.15,58.71 67.92,58.32 arc(67.9,58.32) 67.88,58.32 67.36,58.32 64.02,61.66 61.15,61.66 arc(61.08,61.69) 61.05,61.76 arc(61.02,61.83) 60.95,61.86 60.74,61.86 arc(60.67,61.83) 60.64,61.76 arc(60.61,61.69) 60.54,61.66 60.34,61.66 arc(60.26,61.69) 60.23,61.76 arc(60.2,61.83) 60.13,61.86 59.93,61.86 arc(59.86,61.83) 59.83,61.76 arc(59.8,61.69) 59.73,61.66 59.45,61.66 58.89,61.1 58.14,61.1 58.04,61.2 58.04,61.56 v1(58.26,61.78)
  BOTTOM w0.114: v1(168.09,79.51) 167.8,79.22 166.87,79.22 166.74,79.35 J33.20
MIPI_DPHY1_RX_D3P: length 141.2
  TOP w0.114: J3.77 57.67,64.5 57.75,64.42 57.75,62.05 v1(57.48,61.78)
  ART03 w0.102: v1(57.48,61.78) 57.76,61.51 57.76,61.09 58.02,60.82 59,60.82 59.56,61.38 63.91,61.38 67.25,58.04 67.88,58.04 arc(67.92,58.04) 67.96,58.05 70.2,58.44 arc(70.23,58.44) 70.27,58.44 72.5,58.05 arc(72.54,58.04) 72.59,58.04 78.82,58.04 arc(78.87,58.04) 78.91,58.05 81.32,58.47 arc(81.36,58.47) 81.39,58.47 83.8,58.05 arc(83.84,58.04) 83.89,58.04 84.97,58.04 arc(85.01,58.04) 85.05,58.05 87.71,58.51 arc(87.75,58.51) 87.78,58.51 90.44,58.05 arc(90.48,58.04) 90.52,58.04 91.04,58.04 arc(91.08,58.04) 91.12,58.05 93.77,58.51 arc(93.8,58.51) 93.84,58.51 96.49,58.05 arc(96.53,58.04) 96.57,58.04 97.09,58.04 arc(97.13,58.04) 97.17,58.05 99.82,58.51 arc(99.85,58.51) 99.89,58.51 102.53,58.05 arc(102.57,58.04) 102.61,58.04 103.13,58.04 arc(103.17,58.04) 103.22,58.05 105.86,58.51 arc(105.9,58.51) 105.93,58.51 108.57,58.05 arc(108.62,58.04) 108.66,58.04 109.13,58.04 arc(109.17,58.04) 109.21,58.05 111.88,58.51 arc(111.92,58.52) 111.95,58.51 114.62,58.05 arc(114.66,58.04) 114.7,58.04 115.4,58.04 117.32,59.96 117.32,67.76 120.17,70.6 130.19,70.6 130.3,70.48 130.3,69.74 130.59,69.46 130.99,69.46 131.27,69.74 131.27,70.48 131.39,70.6 131.56,70.6 131.68,70.48 131.68,69.74 131.96,69.46 132.36,69.46 132.64,69.74 132.64,70.48 132.76,70.6 143.32,70.6 145.43,72.71 157.64,72.71 159.7,70.65 163.6,70.65 164.03,71.08 164.03,74.13 165.84,75.94 165.84,78.62 166.18,78.96 167.82,78.96 v1(168.09,78.69)
  BOTTOM w0.114: J33.19 166.74,78.85 166.87,78.98 167.8,78.98 v1(168.09,78.69)
MIPI_DPHY1_TX_CLKN: length 102.2
  TOP w0.114: v1(37.72,52.19) 38.01,52.48 50.3,52.48 55.19,57.37 55.19,64.42 55.27,64.5 J3.65
  ART03 w0.102: v1(4.86,80.23) 4.59,79.96 3.97,79.96 3.63,79.62 3.63,78.91 3.91,78.63 4.88,78.63 5,78.51 5,78.34 4.88,78.22 3.91,78.22 3.63,77.94 3.63,77.56 2.72,76.64 2.72,65.84 3,65.56 3.96,65.56 4.08,65.44 4.08,65.27 3.96,65.15 3,65.15 2.72,64.87 2.72,64.29 3,64.01 3.51,64.01 3.63,63.89 3.63,62.69 3.97,62.35 8.38,62.35 10.06,60.67 10.06,57.15 10.45,56.76 15.81,56.76 15.95,56.62 15.95,53.16 16.24,52.87 17.86,52.87 18.17,53.19 18.17,54.26 18.39,54.48 18.72,54.48 18.89,54.31 18.89,52.85 19.26,52.48 19.79,52.48 20.16,52.85 20.16,54.29 20.35,54.47 20.74,54.47 20.88,54.33 20.88,53.1 21.19,52.79 34.58,52.79 34.91,52.46 37.45,52.46 v1(37.72,52.19)
  BOTTOM w0.114: J15.24 6.21,80.07 6.08,79.94 5.15,79.94 v1(4.86,80.23)
MIPI_DPHY1_TX_CLKP: length 102.3
  TOP w0.114: v1(37.72,53.01) 38.01,52.72 41.09,52.72 arc(41.17,52.75) 41.21,52.83 arc(41.24,52.92) 41.32,52.95 41.55,52.95 arc(41.63,52.92) 41.67,52.83 arc(41.7,52.75) 41.78,52.72 42.01,52.72 arc(42.09,52.75) 42.12,52.83 arc(42.16,52.92) 42.24,52.95 42.47,52.95 arc(42.55,52.92) 42.58,52.83 arc(42.61,52.75) 42.69,52.72 42.92,52.72 arc(43,52.75) 43.04,52.83 arc(43.07,52.92) 43.15,52.95 43.38,52.95 arc(43.46,52.92) 43.49,52.83 arc(43.53,52.75) 43.61,52.72 50.2,52.72 54.95,57.47 54.95,64.42 54.87,64.5 J3.63
  ART03 w0.102: v1(37.72,53.01) 37.45,52.74 37.22,52.74 arc(37.13,52.78) 37.09,52.87 arc(37.05,52.96) 36.96,53 36.82,53 arc(36.72,52.96) 36.69,52.87 arc(36.65,52.78) 36.55,52.74 36.41,52.74 arc(36.32,52.78) 36.28,52.87 arc(36.24,52.96) 36.15,53 36,53 arc(35.91,52.96) 35.87,52.87 arc(35.83,52.78) 35.74,52.74 35.02,52.74 34.69,53.07 21.31,53.07 21.16,53.21 21.16,54.44 20.85,54.75 20.23,54.75 19.88,54.4 19.88,52.97 19.67,52.76 19.38,52.76 19.17,52.97 19.17,54.43 18.84,54.76 18.27,54.76 17.89,54.38 17.89,53.3 17.74,53.15 16.36,53.15 16.23,53.28 16.23,56.73 15.93,57.04 10.57,57.04 10.34,57.27 10.34,60.79 8.5,62.63 4.09,62.63 3.91,62.8 3.91,64 3.63,64.29 3.12,64.29 3,64.41 3,64.75 3.12,64.87 4.08,64.87 4.36,65.16 4.36,65.56 4.08,65.84 3.12,65.84 3,65.96 3,76.53 3.91,77.44 3.91,77.83 4.03,77.94 5,77.94 5.28,78.23 5.28,78.63 5,78.91 4.03,78.91 3.91,79.03 3.91,79.5 4.09,79.68 4.59,79.68 v1(4.86,79.41)
  BOTTOM w0.114: v1(4.86,79.41) 5.15,79.7 6.08,79.7 6.21,79.57 J15.23
MIPI_DPHY1_TX_D0N: length 102.3
  TOP w0.114: J3.73 56.87,64.5 56.79,64.42 56.79,55.98 50.77,49.97 37.96,49.97 v1(37.72,49.73)
  ART03 w0.102: v1(3.3,81.73) 3.03,81.46 1.79,81.46 1.24,80.91 1.24,60.86 1.81,60.3 6.5,60.3 6.93,59.87 6.93,55.3 7.3,54.93 10.01,54.93 10.46,54.47 12.22,54.47 12.93,53.76 12.93,51.4 13.51,50.81 33.05,50.81 33.86,50 37.45,50 v1(37.72,49.73)
  BOTTOM w0.114: v1(3.3,81.73) 3.59,81.44 6.08,81.44 6.21,81.57 J15.27
MIPI_DPHY1_TX_D0P: length 102.2
  TOP w0.114: J3.71 56.47,64.5 56.55,64.42 56.55,56.08 50.67,50.21 43.77,50.21 arc(43.67,50.25) 43.63,50.35 arc(43.59,50.44) 43.49,50.48 43.31,50.48 arc(43.21,50.44) 43.17,50.35 arc(43.13,50.25) 43.03,50.21 42.86,50.21 arc(42.76,50.25) 42.72,50.35 arc(42.68,50.44) 42.58,50.48 42.4,50.48 arc(42.3,50.44) 42.26,50.35 arc(42.22,50.25) 42.12,50.21 41.94,50.21 arc(41.84,50.25) 41.8,50.35 arc(41.76,50.44) 41.66,50.48 41.48,50.48 arc(41.39,50.44) 41.34,50.35 arc(41.3,50.25) 41.21,50.21 38.06,50.21 v1(37.72,50.54)
  ART03 w0.102: v1(37.72,50.54) 37.45,50.28 37.22,50.28 arc(37.13,50.31) 37.09,50.41 arc(37.05,50.5) 36.96,50.54 36.82,50.54 arc(36.72,50.5) 36.69,50.41 arc(36.65,50.31) 36.56,50.28 33.98,50.28 33.16,51.09 13.63,51.09 13.21,51.51 13.21,53.88 12.33,54.75 10.58,54.75 10.12,55.21 7.42,55.21 7.21,55.41 7.21,59.98 6.62,60.58 1.92,60.58 1.52,60.97 1.52,80.8 1.91,81.18 3.03,81.18 v1(3.3,80.91)
  BOTTOM w0.114: v1(3.3,80.91) 3.59,81.2 6.08,81.2 6.21,81.07 J15.26
MIPI_DPHY1_TX_D1N: length 102.2
  TOP w0.114: J3.69 56.07,64.5 55.99,64.42 55.99,56.69 50.51,51.21 39.92,51.21 v1(39.62,50.91)
  ART03 w0.102: v1(39.62,50.91) 39.34,51.2 36.59,51.2 36.21,51.58 35.98,51.58 35.86,51.46 35.86,51.05 35.58,50.76 35.18,50.76 34.89,51.05 34.89,51.46 34.77,51.58 14.29,51.58 13.94,51.92 13.94,54.49 14.21,54.75 15.02,54.75 15.2,54.93 15.2,55.31 15.04,55.47 11.01,55.47 10.64,55.84 9.26,55.84 8.89,56.21 8.89,59.31 8.77,59.43 8.13,59.43 7.85,59.72 7.85,60.12 8.13,60.4 8.77,60.4 8.89,60.52 8.89,60.75 8.28,61.36 2.35,61.36 1.98,61.72 1.98,62.62 2.26,62.9 2.78,62.9 2.9,63.02 2.9,63.19 2.78,63.3 2.26,63.3 1.98,63.59 1.98,78.15 2.28,78.46 2.88,78.46 v1(3.15,78.73)
  BOTTOM w0.114: v1(3.15,78.73) 3.44,78.44 6.08,78.44 6.21,78.57 J15.21
MIPI_DPHY1_TX_D1P: length 102.2
  TOP w0.114: v1(39.62,51.73) 39.9,51.45 41.19,51.45 arc(41.29,51.49) 41.34,51.6 arc(41.38,51.71) 41.49,51.75 41.64,51.75 arc(41.75,51.71) 41.8,51.6 arc(41.84,51.49) 41.95,51.45 42.1,51.45 arc(42.21,51.49) 42.25,51.6 arc(42.3,51.71) 42.41,51.75 42.56,51.75 arc(42.67,51.71) 42.71,51.6 arc(42.76,51.49) 42.86,51.45 43.02,51.45 arc(43.12,51.49) 43.17,51.6 arc(43.21,51.71) 43.32,51.75 43.47,51.75 arc(43.58,51.71) 43.63,51.6 arc(43.67,51.49) 43.78,51.45 43.93,51.45 arc(44.04,51.49) 44.08,51.6 arc(44.13,51.71) 44.24,51.75 44.39,51.75 arc(44.5,51.71) 44.54,51.6 arc(44.58,51.49) 44.69,51.45 50.41,51.45 55.75,56.79 55.75,64.42 55.67,64.5 J3.67
  ART03 w0.102: v1(3.15,77.91) 2.88,78.18 2.4,78.18 2.26,78.04 2.26,63.7 2.38,63.58 2.89,63.58 3.17,63.3 3.17,62.9 2.89,62.62 2.38,62.62 2.26,62.5 2.26,61.84 2.46,61.64 8.4,61.64 9.17,60.86 9.17,60.4 8.89,60.12 8.25,60.12 8.13,60 8.13,59.83 8.25,59.71 8.89,59.71 9.17,59.43 9.17,56.33 9.37,56.12 10.76,56.12 11.13,55.75 15.15,55.75 15.48,55.43 15.48,54.81 15.14,54.47 14.32,54.47 14.22,54.37 14.22,52.04 14.4,51.86 34.89,51.86 35.17,51.57 35.17,51.16 35.29,51.04 35.46,51.04 35.58,51.16 35.58,51.57 35.86,51.86 36.32,51.86 36.7,51.48 39.37,51.48 v1(39.62,51.73)
  BOTTOM w0.114: v1(3.15,77.91) 3.44,78.2 6.08,78.2 6.21,78.07 J15.20
MIPI_DPHY1_TX_D2N: length 102.3
  TOP w0.114: J3.61 54.47,64.5 54.39,64.42 54.39,58.08 50.06,53.75 39.91,53.75 v1(39.62,53.46)
  ART03 w0.102: v1(4.86,77.23) 4.59,76.96 4.19,76.96 3.45,76.22 3.45,68.24 3.78,67.91 5.59,67.91 5.69,67.81 5.69,67.46 5.57,67.34 3.76,67.34 3.48,67.06 3.48,66.66 3.76,66.38 5.5,66.38 5.69,66.19 5.69,64.85 5.55,64.71 4.96,64.71 4.66,64.41 4.66,63.66 5.04,63.29 8.77,63.29 9.3,62.76 10.84,62.76 11.06,62.55 11.06,58.08 11.47,57.67 16.75,57.67 16.99,57.43 16.99,56.03 17.28,55.74 22.13,55.74 22.25,55.63 22.25,54.15 22.62,53.79 23.09,53.79 23.37,54.07 23.37,55.62 23.49,55.74 23.66,55.74 23.78,55.62 23.78,54.07 24.06,53.79 24.46,53.79 24.75,54.07 24.75,55.62 24.86,55.74 25.03,55.74 25.15,55.62 25.15,54.07 25.43,53.79 28.63,53.79 28.93,54.09 28.93,55.55 29.12,55.74 29.75,55.74 29.95,55.55 29.95,54.14 30.3,53.79 30.76,53.79 31.04,54.07 31.04,54.66 31.16,54.78 31.33,54.78 31.45,54.66 31.45,54.07 31.73,53.79 39.3,53.79 v1(39.62,53.46)
  BOTTOM w0.114: J15.18 6.21,77.07 6.08,76.94 5.15,76.94 v1(4.86,77.23)
MIPI_DPHY1_TX_D2P: length 102.2
  TOP w0.114: v1(39.62,54.28) 39.91,53.99 41.1,53.99 arc(41.18,54.02) 41.21,54.1 arc(41.24,54.19) 41.33,54.22 41.55,54.22 arc(41.63,54.19) 41.67,54.1 arc(41.7,54.02) 41.78,53.99 42.01,53.99 arc(42.09,54.02) 42.13,54.1 arc(42.16,54.19) 42.24,54.22 42.47,54.22 arc(42.55,54.19) 42.58,54.1 arc(42.62,54.02) 42.7,53.99 42.93,53.99 arc(43.01,54.02) 43.04,54.1 arc(43.07,54.19) 43.15,54.22 43.38,54.22 arc(43.46,54.19) 43.5,54.1 arc(43.53,54.02) 43.61,53.99 43.84,53.99 arc(43.92,54.02) 43.95,54.1 arc(43.99,54.19) 44.07,54.22 44.3,54.22 arc(44.38,54.19) 44.41,54.1 arc(44.45,54.02) 44.53,53.99 44.75,53.99 arc(44.84,54.02) 44.87,54.1 arc(44.9,54.19) 44.98,54.22 45.21,54.22 arc(45.29,54.19) 45.33,54.1 arc(45.36,54.02) 45.44,53.99 49.96,53.99 54.15,58.18 54.15,64.42 54.07,64.5 J3.59
  ART03 w0.102: v1(4.86,76.41) 4.59,76.68 4.3,76.68 3.73,76.11 3.73,68.36 3.9,68.19 5.7,68.19 5.97,67.92 5.97,67.35 5.69,67.06 3.88,67.06 3.76,66.95 3.76,66.78 3.88,66.66 5.62,66.66 5.97,66.31 5.97,64.73 5.66,64.43 5.08,64.43 4.94,64.29 4.94,63.78 5.16,63.57 8.89,63.57 9.41,63.04 10.95,63.04 11.34,62.66 11.34,58.2 11.58,57.95 16.87,57.95 17.27,57.55 17.27,56.15 17.4,56.02 22.25,56.02 22.53,55.74 22.53,54.27 22.73,54.07 22.98,54.07 23.09,54.19 23.09,55.74 23.38,56.02 23.78,56.02 24.06,55.74 24.06,54.19 24.18,54.07 24.35,54.07 24.47,54.19 24.47,55.74 24.75,56.02 25.15,56.02 25.43,55.74 25.43,54.19 25.55,54.07 28.51,54.07 28.65,54.21 28.65,55.67 29.01,56.02 29.87,56.02 30.23,55.67 30.23,54.26 30.42,54.07 30.65,54.07 30.77,54.19 30.77,54.77 31.05,55.06 31.45,55.06 31.73,54.77 31.73,54.19 31.85,54.07 39.41,54.07 v1(39.62,54.28)
  BOTTOM w0.114: J15.17 6.21,76.57 6.08,76.7 5.15,76.7 v1(4.86,76.41)
MIPI_DPHY1_TX_D3N: length 102.3
  TOP w0.114: v1(37.72,54.72) 38.01,55.01 45.41,55.01 45.68,55.28 45.68,55.98 45.82,56.11 46.01,56.11 46.14,55.98 46.14,55.28 46.42,55.01 46.81,55.01 47.08,55.28 47.08,55.98 47.22,56.11 47.41,56.11 47.54,55.98 47.54,55.28 47.81,55.01 48.2,55.01 48.48,55.28 48.48,55.98 48.61,56.11 48.8,56.11 48.94,55.98 48.94,55.28 49.21,55.01 49.87,55.01 53.59,58.73 53.59,64.42 53.67,64.5 J3.57
  ART03 w0.102: v1(37.72,54.72) 37.45,54.99 37.16,54.99 arc(37.07,54.95) 37.03,54.86 arc(37,54.76) 36.9,54.73 36.76,54.73 arc(36.67,54.76) 36.63,54.86 arc(36.59,54.95) 36.5,54.99 36.35,54.99 arc(36.26,54.95) 36.22,54.86 arc(36.18,54.76) 36.09,54.73 35.95,54.73 arc(35.85,54.76) 35.82,54.86 arc(35.78,54.95) 35.69,54.99 32.5,54.99 32.13,55.35 32.13,56.4 31.93,56.61 18.24,56.61 17.96,56.89 17.96,58.57 17.75,58.77 12.64,58.77 12.27,59.14 12.27,63.48 11.97,63.77 9.4,63.77 8.76,64.4 6.76,64.4 6.45,64.71 6.45,68.42 6.07,68.8 4.56,68.8 4.19,69.17 4.19,75.15 4.68,75.64 6.17,75.64 6.4,75.87 6.4,81.16 6.68,81.44 7.48,81.44 7.59,81.56 7.59,81.73 7.48,81.84 6.68,81.84 6.4,82.13 6.4,82.62 6.73,82.95 7.37,82.95 7.47,83.05 7.47,83.35 7.37,83.45 6.69,83.45 6.2,83.95 4.04,83.95 3.81,83.72 3.81,83.19 4.04,82.96 4.59,82.96 v1(4.86,83.23)
  BOTTOM w0.114: J15.30 6.21,83.07 6.08,82.94 5.15,82.94 v1(4.86,83.23)
MIPI_DPHY1_TX_D3P: length 102.3
  TOP w0.114: v1(37.72,55.54) 38.01,55.25 45.31,55.25 45.44,55.38 45.44,56.08 45.72,56.35 46.11,56.35 46.38,56.08 46.38,55.38 46.52,55.25 46.71,55.25 46.84,55.38 46.84,56.08 47.12,56.35 47.51,56.35 47.78,56.08 47.78,55.38 47.91,55.25 48.1,55.25 48.24,55.38 48.24,56.08 48.51,56.35 48.9,56.35 49.18,56.08 49.18,55.38 49.31,55.25 49.77,55.25 53.35,58.83 53.35,64.42 53.27,64.5 J3.55
  ART03 w0.102: v1(37.72,55.54) 37.45,55.27 32.61,55.27 32.41,55.47 32.41,56.52 32.04,56.89 18.35,56.89 18.24,57 18.24,58.69 17.87,59.05 12.75,59.05 12.55,59.26 12.55,63.59 12.09,64.05 9.51,64.05 8.88,64.68 6.87,64.68 6.73,64.82 6.73,68.53 6.19,69.08 4.67,69.08 4.47,69.28 4.47,75.03 4.8,75.36 6.28,75.36 6.68,75.76 6.68,81.04 6.8,81.16 7.59,81.16 7.87,81.44 7.87,81.84 7.59,82.12 6.8,82.12 6.68,82.24 6.68,82.5 6.85,82.67 7.48,82.67 7.75,82.93 7.75,83.47 7.48,83.73 6.81,83.73 6.31,84.23 3.92,84.23 3.53,83.83 3.53,83.07 3.92,82.68 4.59,82.68 v1(4.86,82.41)
  BOTTOM w0.114: v1(4.86,82.41) 5.15,82.7 6.08,82.7 6.21,82.57 J15.29
OE: length 2.1
  TOP w0.152: U26.8 v1(112.93,48.38)
  BOTTOM w0.152: R223.2 113.29,48.01 v1(112.93,48.38)
ON/OFF: length 5.7
  TOP w0.152: SW4.2 11.53,12.04 11.53,13.5 11.29,13.74 D6.2 C28.1 R19.1
PCIE20_1_REFCLKN: length 103.8
  TOP w0.114: v1(70.62,31.99) 70.33,31.71 70.33,31.46 arc(70.37,31.37) 70.46,31.34 arc(70.55,31.3) 70.59,31.21 70.59,31.01 arc(70.55,30.92) 70.46,30.88 arc(70.37,30.84) 70.33,30.75 70.33,30.55 arc(70.37,30.46) 70.46,30.42 arc(70.55,30.39) 70.59,30.3 70.59,30.09 arc(70.55,30) 70.46,29.97 arc(70.37,29.93) 70.33,29.84 70.33,23.66 70.76,23.23 70.76,22.34 70.84,22.26 J2.15
  BOTTOM w0.114: v1(70.62,31.99) 70.35,31.72 70.35,31.38 70.51,31.22 77.8,31.22 79.44,32.86 83.29,32.86 83.71,33.28 83.71,52.95 92.42,61.66 118.31,61.66 120.64,63.98 120.64,67.27 122.08,68.72 128.69,68.72 arc(128.76,68.75) 128.79,68.82 arc(128.83,68.89) 128.9,68.93 129.15,68.93 arc(129.22,68.89) 129.25,68.82 arc(129.28,68.75) 129.36,68.72 129.64,68.72 130.21,69.29 130.21,70.48 130.08,70.61 J13.49
PCIE20_1_REFCLKP: length 103.8
  TOP w0.114: J2.13 70.44,22.26 70.52,22.34 70.52,23.13 70.09,23.56 70.09,31.71 v1(69.8,31.99)
  BOTTOM w0.114: v1(69.8,31.99) 70.11,31.69 70.11,31.28 70.41,30.98 77.9,30.98 79.54,32.62 83.39,32.62 83.95,33.18 83.95,52.85 92.52,61.42 118.41,61.42 120.88,63.88 120.88,67.17 122.18,68.48 129.74,68.48 130.45,69.19 130.45,70.48 130.58,70.61 J13.47
PCIE20_1_RXN: length 108.6
  TOP w0.165: J2.5 68.84,22.35 68.79,22.4 68.79,23.13 68.03,23.88 68.03,26.36 arc(68.08,26.48) 68.21,26.53 arc(68.33,26.58) 68.38,26.7 68.38,27.02 arc(68.33,27.14) 68.21,27.19 arc(68.08,27.24) 68.03,27.36 68.03,29.52 arc(68.09,29.66) 68.23,29.71 arc(68.37,29.77) 68.43,29.91 68.43,30.18 arc(68.37,30.32) 68.23,30.37 arc(68.09,30.43) 68.03,30.57 68.03,31.5 v1(68.3,31.76)
  BOTTOM w0.165: J13.43 131.58,70.54 131.68,70.43 131.68,69.36 130.18,67.86 122.47,67.86 121.37,66.76 121.37,63.35 118.76,60.74 94,60.74 84.7,51.44 84.7,31.68 84.09,31.08 79.04,31.08 78.32,30.36 68.34,30.36 68.01,30.69 68.01,31.6 68.17,31.76 v1(68.3,31.76)
PCIE20_1_RXP: length 108.6
  TOP w0.165: v1(67.48,31.76) 67.74,31.5 67.74,23.76 68.49,23.01 68.49,22.4 68.44,22.35 J2.3
  BOTTOM w0.165: v1(67.48,31.76) 67.72,31.53 67.72,30.56 68.22,30.06 78.44,30.06 79.17,30.79 84.21,30.79 84.99,31.56 84.99,51.32 94.12,60.45 118.89,60.45 121.67,63.23 121.67,66.64 122.59,67.56 130.3,67.56 131.97,69.23 131.97,70.43 132.08,70.54 J13.41
PCIE20_1_TXN: length 101.8
  TOP w0.165: v1(69.52,28.01) 69.26,27.74 69.26,27.45 arc(69.3,27.34) 69.41,27.29 arc(69.52,27.25) 69.57,27.14 69.57,26.79 arc(69.52,26.68) 69.41,26.63 arc(69.3,26.59) 69.26,26.48 69.26,26.13 arc(69.3,26.02) 69.41,25.97 arc(69.52,25.93) 69.57,25.81 69.57,25.47 arc(69.52,25.36) 69.41,25.31 arc(69.3,25.27) 69.26,25.15 69.26,24.03 69.59,23.7 69.59,22.4 69.64,22.35 J2.9
  BOTTOM w0.165: C252.1 134.49,59.74 134.85,59.38 134.85,58.43 134.5,58.08 121.51,58.08 121,58.58 95.29,58.58 86.98,50.28 86.98,28.58 86.28,27.88 73.86,27.88 73.26,27.28 69.42,27.28 69.26,27.45 69.26,27.74 v1(69.52,28.01)
PCIE20_1_TXP: length 102.1
  TOP w0.165: v1(68.7,28.01) 68.96,27.74 68.96,23.91 69.29,23.58 69.29,22.4 69.24,22.35 J2.7
  BOTTOM w0.165: v1(68.7,28.01) 68.96,27.74 68.96,27.33 69.3,26.99 73.38,26.99 73.98,27.59 86.4,27.59 87.27,28.46 87.27,50.15 95.41,58.29 120.88,58.29 121.39,57.78 134.62,57.78 135.15,58.31 135.15,59.38 135.51,59.74 C251.1
PCIE20_2_REFCLKN: length 112.3
  TOP w0.114: J2.31 74.04,22.26 73.96,22.34 73.96,23.6 v2(74.23,23.87) ; J23.11 140.5,70.93 140.22,70.65 140.22,69.5 v1(140.51,69.21)
  BOTTOM w0.114: v2(74.23,23.87) 73.96,24.13 73.96,24.61 74.23,24.88 88.87,24.88 89.48,25.49 89.48,48.95 96.67,56.14 114.94,56.14 115.96,55.12 119.91,55.12 121.25,56.45 135.09,56.45 136.32,57.68 136.32,67.46 136.6,67.74 139.85,67.74 140.22,68.11 140.22,68.93 v1(140.51,69.21)
PCIE20_2_REFCLKP: length 112.3
  TOP w0.114: J23.13 139.7,70.93 139.98,70.65 139.98,69.5 v1(139.69,69.21) ; v2(73.45,23.87) 73.72,23.6 73.72,22.34 73.64,22.26 J2.29
  BOTTOM w0.114: v1(139.69,69.21) 139.98,68.93 139.98,68.21 139.75,67.98 136.5,67.98 136.08,67.56 136.08,57.78 134.99,56.69 121.15,56.69 119.81,55.36 116.06,55.36 115.04,56.38 96.57,56.38 89.24,49.05 89.24,25.59 88.77,25.12 74.13,25.12 73.72,24.71 73.72,24.13 v2(73.45,23.87)
PCIE20_2_RXN: length 103.5
  TOP w0.165: J2.21 72.04,22.35 71.99,22.4 71.99,23.35 71.55,23.79 71.55,27.72 v1(71.82,27.98) ; v1(132.51,67.94) 132.25,68.2 132.25,70.67 132.5,70.92 J23.23
  BOTTOM w0.165: v1(71.82,27.98) 71.58,28.22 71.58,28.63 71.74,28.79 84.99,28.79 86,29.81 86,50.61 94.89,59.49 120.34,59.49 122.81,61.96 122.81,64.26 124.08,65.53 131.48,65.53 132.25,66.29 132.25,67.68 v1(132.51,67.94)
PCIE20_2_RXP: length 103.5
  TOP w0.165: J2.19 71.64,22.35 71.69,22.4 71.69,23.23 71.26,23.67 71.26,27.72 v1(71,27.98) ; J23.25 131.7,70.92 131.95,70.67 131.95,68.2 v1(131.69,67.94)
  BOTTOM w0.165: v1(71,27.98) 71.28,28.27 71.28,28.75 71.62,29.09 84.87,29.09 85.71,29.93 85.71,50.73 94.76,59.78 120.21,59.78 122.52,62.08 122.52,64.38 123.96,65.82 131.36,65.82 131.95,66.41 131.95,67.68 v1(131.69,67.94)
PCIE20_2_TXN: length 80.9
  TOP w0.165: v2(73.03,24.96) 72.79,24.71 72.79,22.4 72.84,22.35 J2.25 ; C214.1 119.02,58.95 119.02,57.67 v1(119.28,57.4)
  BOTTOM w0.165: v1(119.28,57.4) 119.02,57.14 119.02,56.55 118.52,56.05 116.8,56.05 115.74,57.11 96.01,57.11 88.46,49.56 88.46,26.67 87.78,26 73.12,26 72.79,25.67 72.79,25.2 v2(73.03,24.96)
PCIE20_2_TXP: length 80.9
  TOP w0.165: v2(72.25,24.96) 72.49,24.71 72.49,22.4 72.44,22.35 J2.23 ; v1(118.46,57.4) 118.73,57.67 118.73,58.95 C215.1
  BOTTOM w0.165: v2(72.25,24.96) 72.49,25.2 72.49,25.79 73,26.29 87.66,26.29 88.16,26.79 88.16,49.68 95.89,57.41 115.86,57.41 116.93,56.34 118.4,56.34 118.73,56.67 118.73,57.14 v1(118.46,57.4)
PCIE30_PORT0_REF_CLKN: length 64.3
  TOP w0.114: v2(70.23,17.67) 70.5,17.4 70.5,16.31 70.92,15.89 73.5,15.89 73.96,16.35 73.96,17.96 74.04,18.04 J2.32 ; v1(90.11,40.52) 90.4,40.81 90.4,42.2 90.77,42.57 99.28,42.57 99.5,42.8 99.5,43.7 99.99,44.19 101.28,44.19 101.67,44.58 v1(102.12,44.58)
  BOTTOM w0.114: v1(90.11,40.52) 90.43,40.2 90.43,37.31 90.81,35.12 90.36,32.53 90.9,29.4 90.47,26.91 90.43,26.43 90.43,26.13 arc(90.27,25.35) 89.84,24.7 89.61,24.48 arc(88.93,24.02) 88.13,23.86 84.86,23.86 arc(84.85,23.86) 84.83,23.86 arc(84.83,23.86) 84.82,23.86 arc(84.66,23.86) 84.5,23.84 81.69,23.35 arc(81.67,23.35) 81.66,23.34 81.43,23.34 arc(81.41,23.35) 81.39,23.35 78.27,23.89 arc(78.19,23.9) 78.11,23.89 74.99,23.35 arc(74.97,23.35) 74.95,23.34 71.35,23.34 arc(70.75,23.1) 70.5,22.49 70.5,17.94 v2(70.23,17.67)
PCIE30_PORT0_REF_CLKP: length 64.2
  TOP w0.114: J2.30 73.64,18.04 73.72,17.96 73.72,16.45 73.4,16.13 71.02,16.13 70.74,16.41 70.74,17.4 v2(71.01,17.67) ; v1(102.12,43.56) 101.67,43.56 101.28,43.95 100.09,43.95 99.75,43.6 99.75,42.7 99.38,42.33 90.87,42.33 90.64,42.1 90.64,40.81 v1(90.93,40.52)
  BOTTOM w0.114: v2(71.01,17.67) 70.74,17.94 70.74,18.18 arc(70.78,18.27) 70.87,18.31 arc(70.96,18.35) 70.99,18.44 70.99,18.64 arc(70.96,18.73) 70.87,18.77 arc(70.78,18.81) 70.74,18.89 70.74,19.1 arc(70.78,19.19) 70.87,19.23 arc(70.96,19.26) 70.99,19.35 70.99,19.56 arc(70.96,19.65) 70.87,19.68 arc(70.78,19.72) 70.74,19.81 70.74,20.01 arc(70.78,20.1) 70.87,20.14 arc(70.96,20.18) 70.99,20.27 70.99,20.47 arc(70.96,20.56) 70.87,20.6 arc(70.78,20.63) 70.74,20.72 70.74,20.93 arc(70.78,21.02) 70.87,21.05 arc(70.96,21.09) 70.99,21.18 70.99,21.38 arc(70.96,21.47) 70.87,21.51 arc(70.78,21.55) 70.74,21.64 70.74,22.49 arc(70.92,22.93) 71.35,23.1 74.95,23.1 arc(74.99,23.11) 75.03,23.11 78.15,23.65 arc(78.19,23.66) 78.23,23.65 81.35,23.11 arc(81.39,23.11) 81.43,23.1 81.66,23.1 arc(81.7,23.11) 81.74,23.11 84.54,23.6 arc(84.67,23.62) 84.81,23.62 arc(84.83,23.62) 84.86,23.62 88.13,23.62 arc(89.02,23.8) 89.78,24.3 90.01,24.53 arc(90.5,25.26) 90.67,26.13 90.67,26.42 90.71,26.88 91.15,29.4 90.6,32.53 91.05,35.12 90.67,37.33 90.67,40.25 v1(90.93,40.52)
PCIE30_PORT0_RX0N: length 157.6
  TOP w0.165: J19.41 161.79,92.91 161.9,92.81 161.9,91.16 arc(161.85,91.04) 161.73,91 arc(161.62,90.95) 161.57,90.83 161.57,90.5 arc(161.62,90.38) 161.73,90.34 arc(161.85,90.29) 161.9,90.17 161.9,89.84 arc(161.85,89.72) 161.73,89.68 arc(161.62,89.63) 161.57,89.51 161.57,89.18 arc(161.62,89.06) 161.73,89.02 arc(161.85,88.97) 161.9,88.85 161.9,88.07 v1(161.59,87.77) ; v2(72.2,16.88) 71.98,17.09 71.98,17.89 72.04,17.95 J2.22
  BOTTOM w0.165: v1(161.59,87.77) 161.9,87.47 161.9,87.09 161.04,86.24 arc(160.53,85.9) 159.92,85.77 159.31,85.77 arc(158.37,85.59) 157.57,85.06 153.29,80.77 arc(152.91,80.21) 152.78,79.54 arc(152.68,79.06) 152.41,78.64 152.35,78.58 148.6,74.84 arc(147.57,73.29) 147.21,71.47 147.21,66.72 147.19,66.52 146.63,63.28 147.19,60.04 147.21,59.84 147.21,56.37 arc(147.11,55.88) 146.83,55.47 146.24,54.87 arc(145.64,54.47) 144.93,54.33 138.9,54.33 135.52,53.74 132.14,54.33 127.85,54.33 arc(126.88,54.14) 126.06,53.59 125.6,53.13 arc(124.87,52.65) 124.02,52.48 117.81,52.48 114.51,51.9 111.21,52.48 110.37,52.48 105.86,51.69 101.36,52.48 99.63,52.48 arc(98.66,52.28) 97.84,51.73 96.02,49.91 94.95,48.45 93.75,45.8 93.75,41.65 93.75,41.65 93.75,41.49 93.19,38.26 93.73,35.16 93.28,32.61 93.31,32.26 93.98,28.43 93.29,24.48 93.29,21.47 arc(93.01,20.78) 92.33,20.5 89.26,20.5 arc(89.23,20.5) 89.2,20.5 87.15,20.86 arc(86.9,20.88) 86.64,20.86 84.59,20.5 arc(84.56,20.5) 84.53,20.5 arc(84.51,20.5) 84.48,20.5 82.1,20.92 arc(81.99,20.93) 81.89,20.92 79.51,20.5 arc(79.48,20.5) 79.45,20.5 75.9,20.5 arc(75.1,20.34) 74.43,19.89 74.12,19.58 arc(73.66,18.89) 73.49,18.07 73.49,17.48 arc(73.46,17.39) 73.36,17.35 arc(73.27,17.31) 73.23,17.22 73.23,16.82 arc(73.27,16.73) 73.36,16.69 arc(73.46,16.65) 73.49,16.56 73.49,16.16 73.25,15.92 72.24,15.92 71.95,16.21 71.95,16.63 v2(72.2,16.88)
